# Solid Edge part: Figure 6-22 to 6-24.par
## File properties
Author: CADCIM
Template: Normal.par
Last saved by: CADCIM_Sonam
Revision: 6
Application: Solid Edge
Accuracy: 0.99
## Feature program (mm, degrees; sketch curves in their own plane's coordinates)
sketch for "unnamed Protrusion 1" plane through (0, 0, 0) normal (0, -1, 0) x-axis (1, 0, 0)
  line (-47.9688, 40.4319) -> (-47.9688, 0)
  line (-47.9688, 0) -> (40.7735, 0)
  line (40.7735, 0) -> (11.4256, 32.2563)
  arc centre (-7.0661, 15.4319) radius 25 from (11.4256, 32.2563) to (-7.0661, 40.4319) ccw
  line (-7.0661, 40.4319) -> (-47.9688, 40.4319)
extrude "unnamed Protrusion 1" add finite 57.15 symmetric
sketch for "ExtrudedProtrusion_3" plane through (18.5879, 0, 24.3842) normal (0.739666, 0, 0.672975) x-axis (0, 1, 0)
  circle centre (0, -8.0136) radius 16.4586
extrude "ExtrudedProtrusion_3" add finite 41.275 along +normal
fillet "Round_9" radius 5
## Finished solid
Body 1: solid body, 11 faces, 23 edges, 14 vertices.
  Faces by surface: plane 7, cylinder 2, blend 1, torus 1
  Edges by curve: line 15, circle 7, intersection 1
Bounding box of the edges (mm; curved faces can reach further): 113.556 x 57.150 x 58.408, from (-47.9688, -28.575, 0) to (65.5868, 28.575, 58.4077).
Cylindrical faces by radius (mm): R16.4586 x1, R25 x1
Toroidal faces (ring radius, tube radius in mm): R21.4586 r5 x1
Planar faces by outward normal: +y 1, +z 1, -x 1, -y 1, -z 1, oblique 2
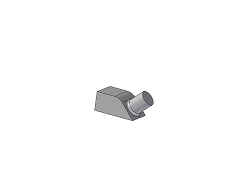
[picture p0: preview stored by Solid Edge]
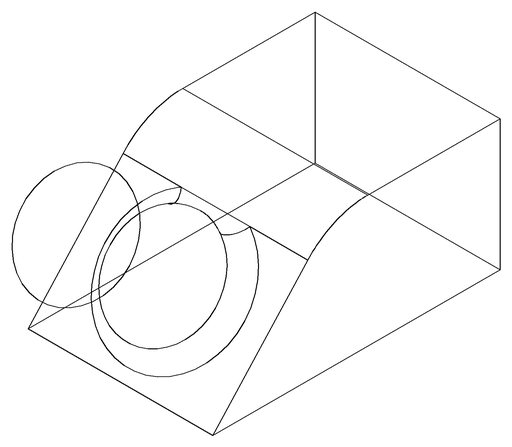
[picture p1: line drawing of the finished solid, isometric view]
